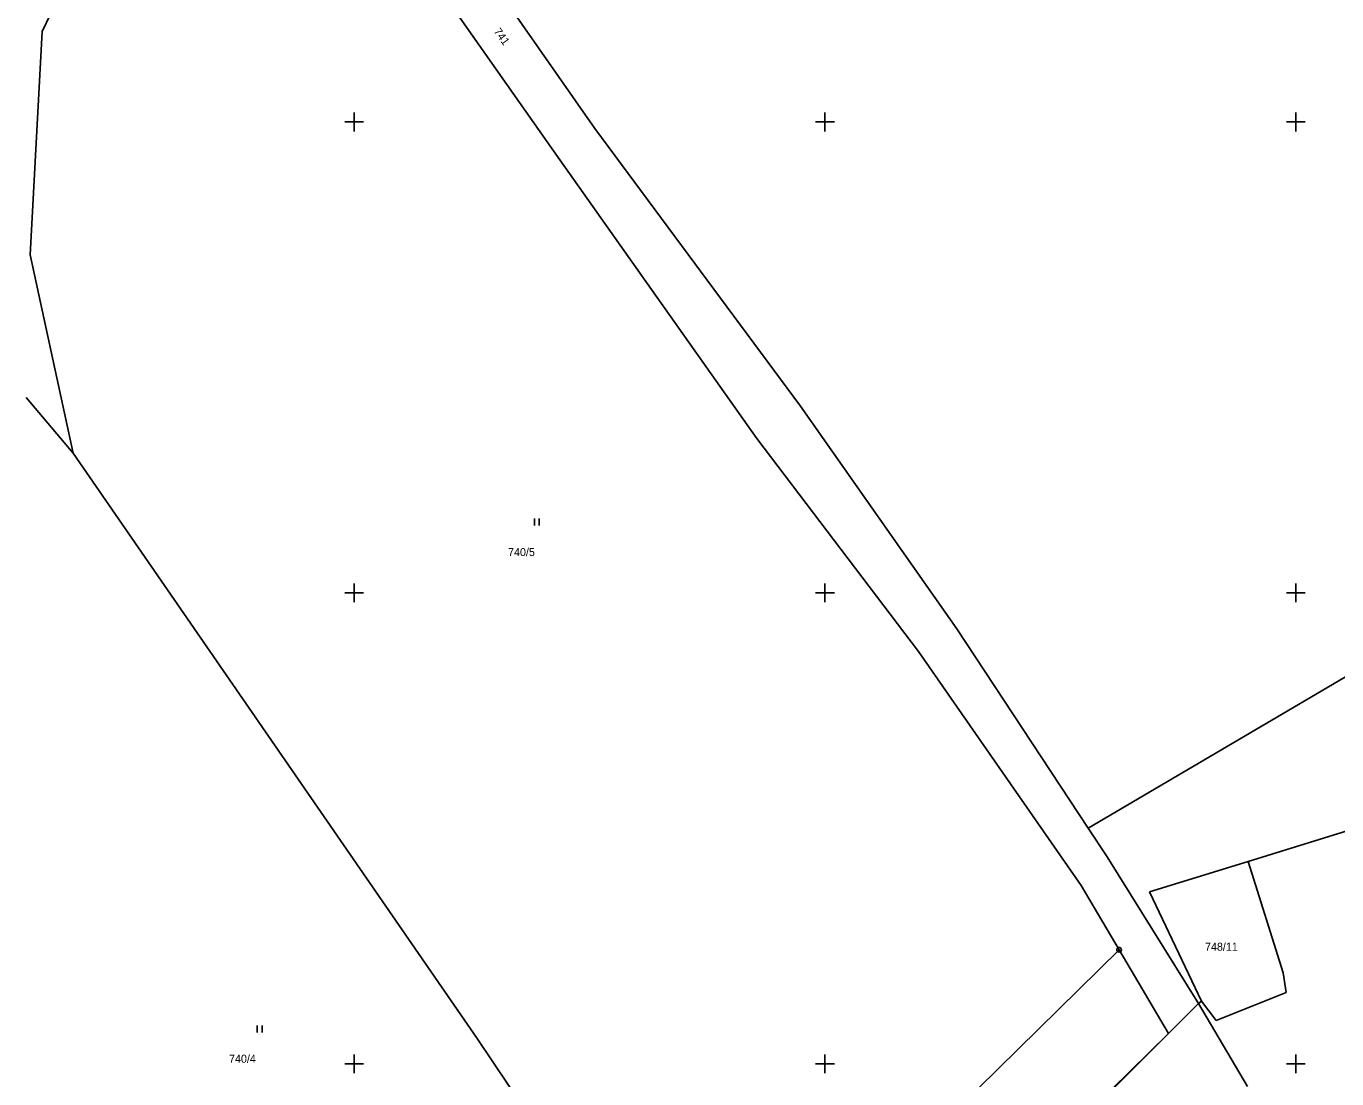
# Model space of a CAD drawing. Extents: x -493648 to -493033, y -1127718 to -1127026.
# Drawn here: x -493634.8 to -493495.7, y -1127551.6 to -1127439.8 of the extents above; entities that cross this region are included whole.
import ezdxf

# ---------------------------------------------------------------- set-up
doc = ezdxf.new("R2010")
doc.units = 0
doc.layers.add('katastrální mapa', color=7, linetype='Continuous')
doc.layers.add('síť', color=7, linetype='Continuous')

msp = doc.modelspace()

# ---------------------------------------------------------------- linework, layer by layer
at = {"layer": 'katastrální mapa'}
for p, q in [((-493594.76, -1127421.62), (-493574.44, -1127450.7)), ((-493599.13, -1127424.19), (-493578.17, -1127454.01)), ((-493629.48, -1127432.72), (-493633.12, -1127440.38)), ((-493633.12, -1127440.38), (-493634.41, -1127464.1)), ((-493574.44, -1127450.7), (-493552.61, -1127480.18)), ((-493578.17, -1127454.01), (-493557.24, -1127483.62)), ((-493634.41, -1127464.1), (-493629.82, -1127485.15)), ((-493522.04, -1127524.99), (-493433.93, -1127473.06)), ((-493629.82, -1127485.15), (-493634.82, -1127479.27)), ((-493552.61, -1127480.18), (-493536.01, -1127503.8)), ((-493557.24, -1127483.62), (-493540.07, -1127506.21)), ((-493629.82, -1127485.15), (-493586.95, -1127547.3)), ((-493580.84, -1127492.84), (-493580.84, -1127492.09)), ((-493580.34, -1127492.09), (-493580.34, -1127492.84)), ((-493536.01, -1127503.8), (-493522.04, -1127524.99)), ((-493540.07, -1127506.21), (-493522.78, -1127531.08)), ((-493490.2, -1127523.9), (-493505.05, -1127528.5)), ((-493522.04, -1127524.99), (-493520.05, -1127528.01)), ((-493520.05, -1127528.01), (-493510.34, -1127543.6)), ((-493505.05, -1127528.5), (-493515.54, -1127531.75)), ((-493501.36, -1127540.32), (-493505.05, -1127528.5)), ((-493522.78, -1127531.08), (-493518.76, -1127537.89)), ((-493515.54, -1127531.75), (-493510.01, -1127543.35)), ((-493563.39, -1127581.71), (-493518.76, -1127537.89)), ((-493518.76, -1127537.89), (-493513.51, -1127546.77)), ((-493501.01, -1127542.43), (-493501.36, -1127540.32)), ((-493508.47, -1127545.38), (-493501.01, -1127542.43)), ((-493510.34, -1127543.6), (-493511.3, -1127544.55)), ((-493510.01, -1127543.35), (-493510.34, -1127543.6)), ((-493510.34, -1127543.6), (-493505.13, -1127552.42)), ((-493510.01, -1127543.35), (-493508.47, -1127545.38)), ((-493513.51, -1127546.77), (-493511.3, -1127544.55)), ((-493610.28, -1127546.67), (-493610.28, -1127545.92)), ((-493609.78, -1127545.92), (-493609.78, -1127546.67)), ((-493557.23, -1127589.69), (-493513.51, -1127546.77)), ((-493513.51, -1127546.77), (-493556.54, -1127589.59)), ((-493586.95, -1127547.3), (-493566.1, -1127578.21))]:
    msp.add_line(p, q, dxfattribs=at)
for radius in [0.25, 0.005]:
    msp.add_circle((-493518.76, -1127537.89), radius, dxfattribs=at)
at = {"layer": 'síť'}
for p, q in [((-493600, -1127449), (-493600, -1127451)), ((-493550, -1127449), (-493550, -1127451)), ((-493500, -1127449), (-493500, -1127451)), ((-493601, -1127450), (-493599, -1127450)), ((-493551, -1127450), (-493549, -1127450)), ((-493501, -1127450), (-493499, -1127450)), ((-493600, -1127499), (-493600, -1127501)), ((-493550, -1127499), (-493550, -1127501)), ((-493500, -1127499), (-493500, -1127501)), ((-493601, -1127500), (-493599, -1127500)), ((-493551, -1127500), (-493549, -1127500)), ((-493501, -1127500), (-493499, -1127500)), ((-493600, -1127549), (-493600, -1127551)), ((-493550, -1127549), (-493550, -1127551)), ((-493500, -1127549), (-493500, -1127551)), ((-493601, -1127550), (-493599, -1127550)), ((-493551, -1127550), (-493549, -1127550)), ((-493501, -1127550), (-493499, -1127550))]:
    msp.add_line(p, q, dxfattribs=at)

# ---------------------------------------------------------------- texts
at = {"layer": 'katastrální mapa'}
msp.add_text('741', height=0.849996, rotation=305.0999972, dxfattribs=at).set_placement((-493585.21, -1127440.39))
for s, p in [('740/5', (-493583.65, -1127496.09)), ('748/11', (-493509.64, -1127537.99)), ('740/4', (-493613.28, -1127549.88))]:
    msp.add_text(s, height=0.849996, dxfattribs=at).set_placement(p)

doc.saveas('drawing.dxf')
